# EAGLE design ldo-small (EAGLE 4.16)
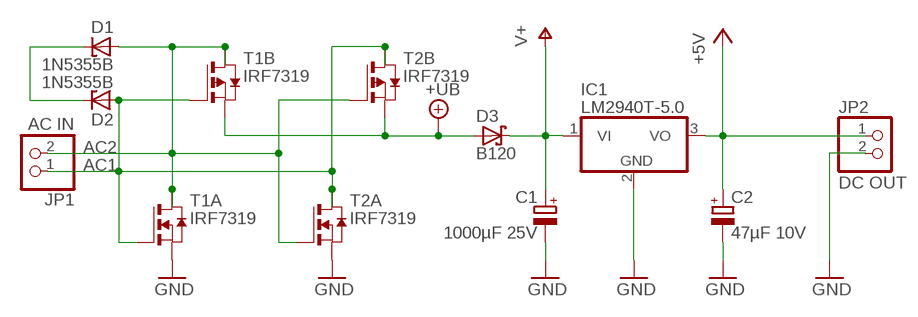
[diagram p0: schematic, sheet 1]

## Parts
C1  1000µF 25V  CPOL-EUTT5D11L  [TT5D11L]
C2  47µF 10V  CPOL-EUCT6032  [CT6032]
D1  1N5355B  1N5333  [C1702-15]
D2  1N5355B  1N5333  [C1702-15]
D3  B120  SCHOTTKY-DIODESMD  [SMB]
IC1  LM2940T-5.0  7805T  [TO220H]
JP1  AC IN  PINHD-1X2  [1X02]
JP2  DC OUT  PINHD-1X2  [1X02]
T1  IRF7319  PN_MOSFET-SO8  [SO8]
T2  IRF7319  PN_MOSFET-SO8  [SO8]

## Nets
+5V: C2.+ IC1.3(VO) JP2.1
+UB: D3.A T1.3(B:S) T2.3(B:S)
AC: D1.C D2.C
AC1: D2.A JP1.1 T1.2(A:G) T1.4(B:G) T2.5(B:D) T2.6(B:D2) T2.7(A:D) T2.8(A:D2)
AC2: D1.A JP1.2 T1.5(B:D) T1.6(B:D2) T1.7(A:D) T1.8(A:D2) T2.2(A:G) T2.4(B:G)
GND: C1.- C2.- IC1.2(GND) JP2.2 T1.1(A:S) T2.1(A:S)
V+: C1.+ D3.C IC1.1(VI)

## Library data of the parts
C1 C2 = rcl:CPOL-EU: POLARIZED CAPACITOR, European symbol
D1 D2 = diode:1N5333: Z DIODE
D3 = diode:SCHOTTKY-DIODE: Schottky Diode
IC1 = linear:78*: Positive VOLTAGE REGULATOR Source: http://cache.national.com/ds/LM/LM78L05.pdf http://www.fairchildsemi.com/ds/LM/LM7805.pdf
JP1 JP2 = pinhead:PINHD-1X2: PIN HEADER
T1 T2 = zetex:PN_MOSFET-: DUAL N AND P-CHANNEL ENHANCEMENT MODE MOSFET source ZXMD63C02.pdf from http://www.zetex.com/

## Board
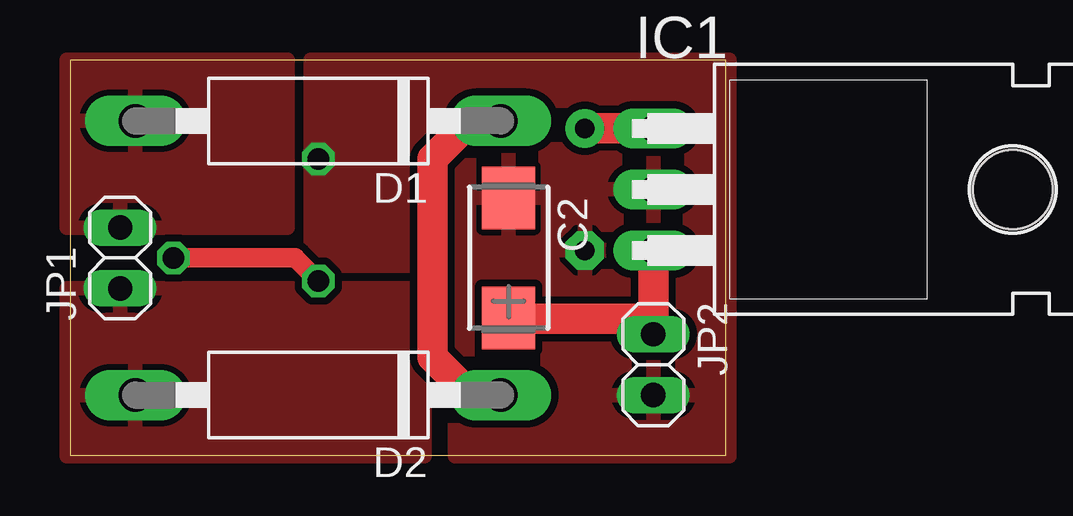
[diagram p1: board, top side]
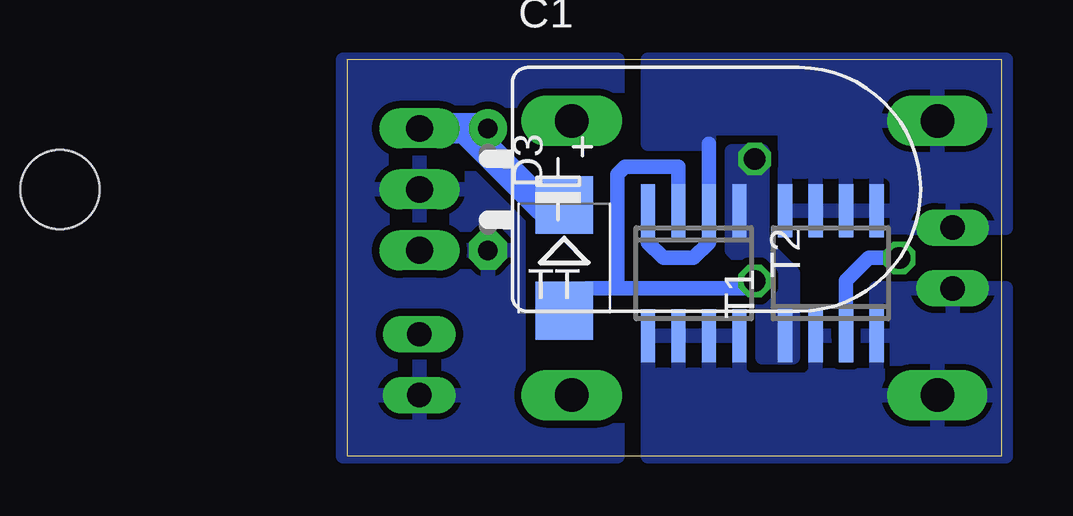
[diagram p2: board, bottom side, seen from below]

Size 27.29 x 16.5 mm. Coordinates in mm from the lower left corner, seen from the top.
Outline: 0,16.5 27.29,16.5 27.29,0 0,0 0,16.5
Copper layers (1*16): Top 0.035mm / dielectric 1.5mm / Bottom 0.035mm
Design rules "default": minimum track width 8mil, minimum drill 24mil, track to track 12mil, track to pad 12mil, pad to pad 12mil, via to via 12mil, smd to smd 8mil, copper to edge 0mil, drill to drill 12mil, minimum pad ring 10mil, minimum via ring 8mil, stop-mask expansion 4mil, vias tented up to drill 0mil, thermal gap 10mil

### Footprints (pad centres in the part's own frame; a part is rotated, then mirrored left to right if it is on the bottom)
TT5D11L = drill 0.813 pad 1.6 round: + -2.54,0 | drill 0.813 pad 1.6 octagon: - 2.54,0
CT6032 = smd 2.6 x 2.2: + 2.5,0; - -2.5,0
C1702-15 = drill 1.397 long: A 7.62,0; C -7.62,0
SMB = smd 2.4 x 2.4: A 2.2,0; C -2.2,0
TO220H = drill 1.118 long: 1 -2.54,-10.16; 2 0,-10.16; 3 2.54,-10.16 | hole 3.302: 0,4.826
1X02 = drill 1.016 long: 1 -1.27,0; 2 1.27,0
SO8 = smd 0.6 x 2.2: 1 -1.905,-2.6; 2 -0.635,-2.6; 3 0.635,-2.6; 4 1.905,-2.6; 5 1.905,2.6; 6 0.635,2.6; 7 -0.635,2.6; 8 -1.905,2.6

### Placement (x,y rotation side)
C1  21.43,11.11 270 bottom
C2  18.25,8.25 270 top
D1  10.31,13.97 180 top
D2  10.31,2.54 180 top
D3  18.25,8.25 270 bottom
IC1  34.44,11.11 270 top
JP1  2.06,8.25 90 top
JP2  24.28,3.8 270 top
T1  7.14,7.62 0 bottom
T2  12.85,7.62 180 bottom

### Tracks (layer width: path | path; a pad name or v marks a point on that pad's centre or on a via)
+5V
  Top 1.27: 24.28,5.71 IC1.3 | C2.+ 18.25,5.71 24.28,5.71 | 24.28,5.71 JP2.1
+UB  (via drill 0.9)
  Top 0.813: v10.31,7.3 9.36,8.25 v4.28,8.25
  Bottom 0.61: 13.49,10.16 T2.3 13.49,12.06 15.71,12.06 16.03,11.74 16.03,6.98 | v10.31,7.3 10.63,6.98 16.03,6.98 | 18.25,6.03 D3.A 17.32,6.98 16.03,6.98 | T1.3 6.5,7.3 5.55,8.25 v4.28,8.25
AC
  Top 1.27: D1.C 16.66,13.97 15.08,12.38 15.08,4.12 16.66,2.54 D2.C
AC1
  Bottom 0.61: T2.8 10.95,5.71
  pour Bottom: -0.17,6.98 5.23,6.98 5.23,5.71 7.77,5.71 7.77,3.49 8.09,3.17 10.63,3.17 10.95,3.49 10.95,5.71 14.76,5.71 14.76,-0.01 -0.17,-0.01
  pour Top: -0.17,6.98 14.76,6.98 14.76,-0.01 -0.17,-0.01
AC2
  Bottom 0.61: T2.4 14.76,8.89 14.12,8.25 12.85,8.25 12.22,8.89 T2.2 12.22,13.01
  pour Bottom: -0.17,16.5 14.76,16.5 14.76,13.01 12.22,13.01 12.22,13.65 9.04,13.65 9.04,9.52 -0.17,9.52
  pour Top: -0.17,9.52 9.04,9.52 9.04,16.5 -0.17,16.5
GND  (via drill 0.9)
  other vias: 10.31,12.38
  pour Bottom: 27.46,16.5 16.03,16.5 16.03,13.01 20.16,13.01 20.16,3.49 16.03,3.49 16.03,-0.01 27.46,-0.01
  pour Top: 10,16.5 27.46,16.5 27.46,-0.01 16.03,-0.01 16.03,7.93 10,7.93
  pour Bottom (no thermals): 10,12.7 11.27,12.7 11.27,8.57 10,7.3 10,4.12 8.73,4.12 8.73,7.62 10,8.89
V+
  Top 1.27: IC1.1 C1.+
  Bottom 1.27: D3.C 19.18,10.45 22.38,13.65 | 22.38,13.65 IC1.1 | 22.38,13.65 C1.+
